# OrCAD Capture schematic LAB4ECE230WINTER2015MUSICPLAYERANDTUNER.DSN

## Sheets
1 part2LCDtuner: size A
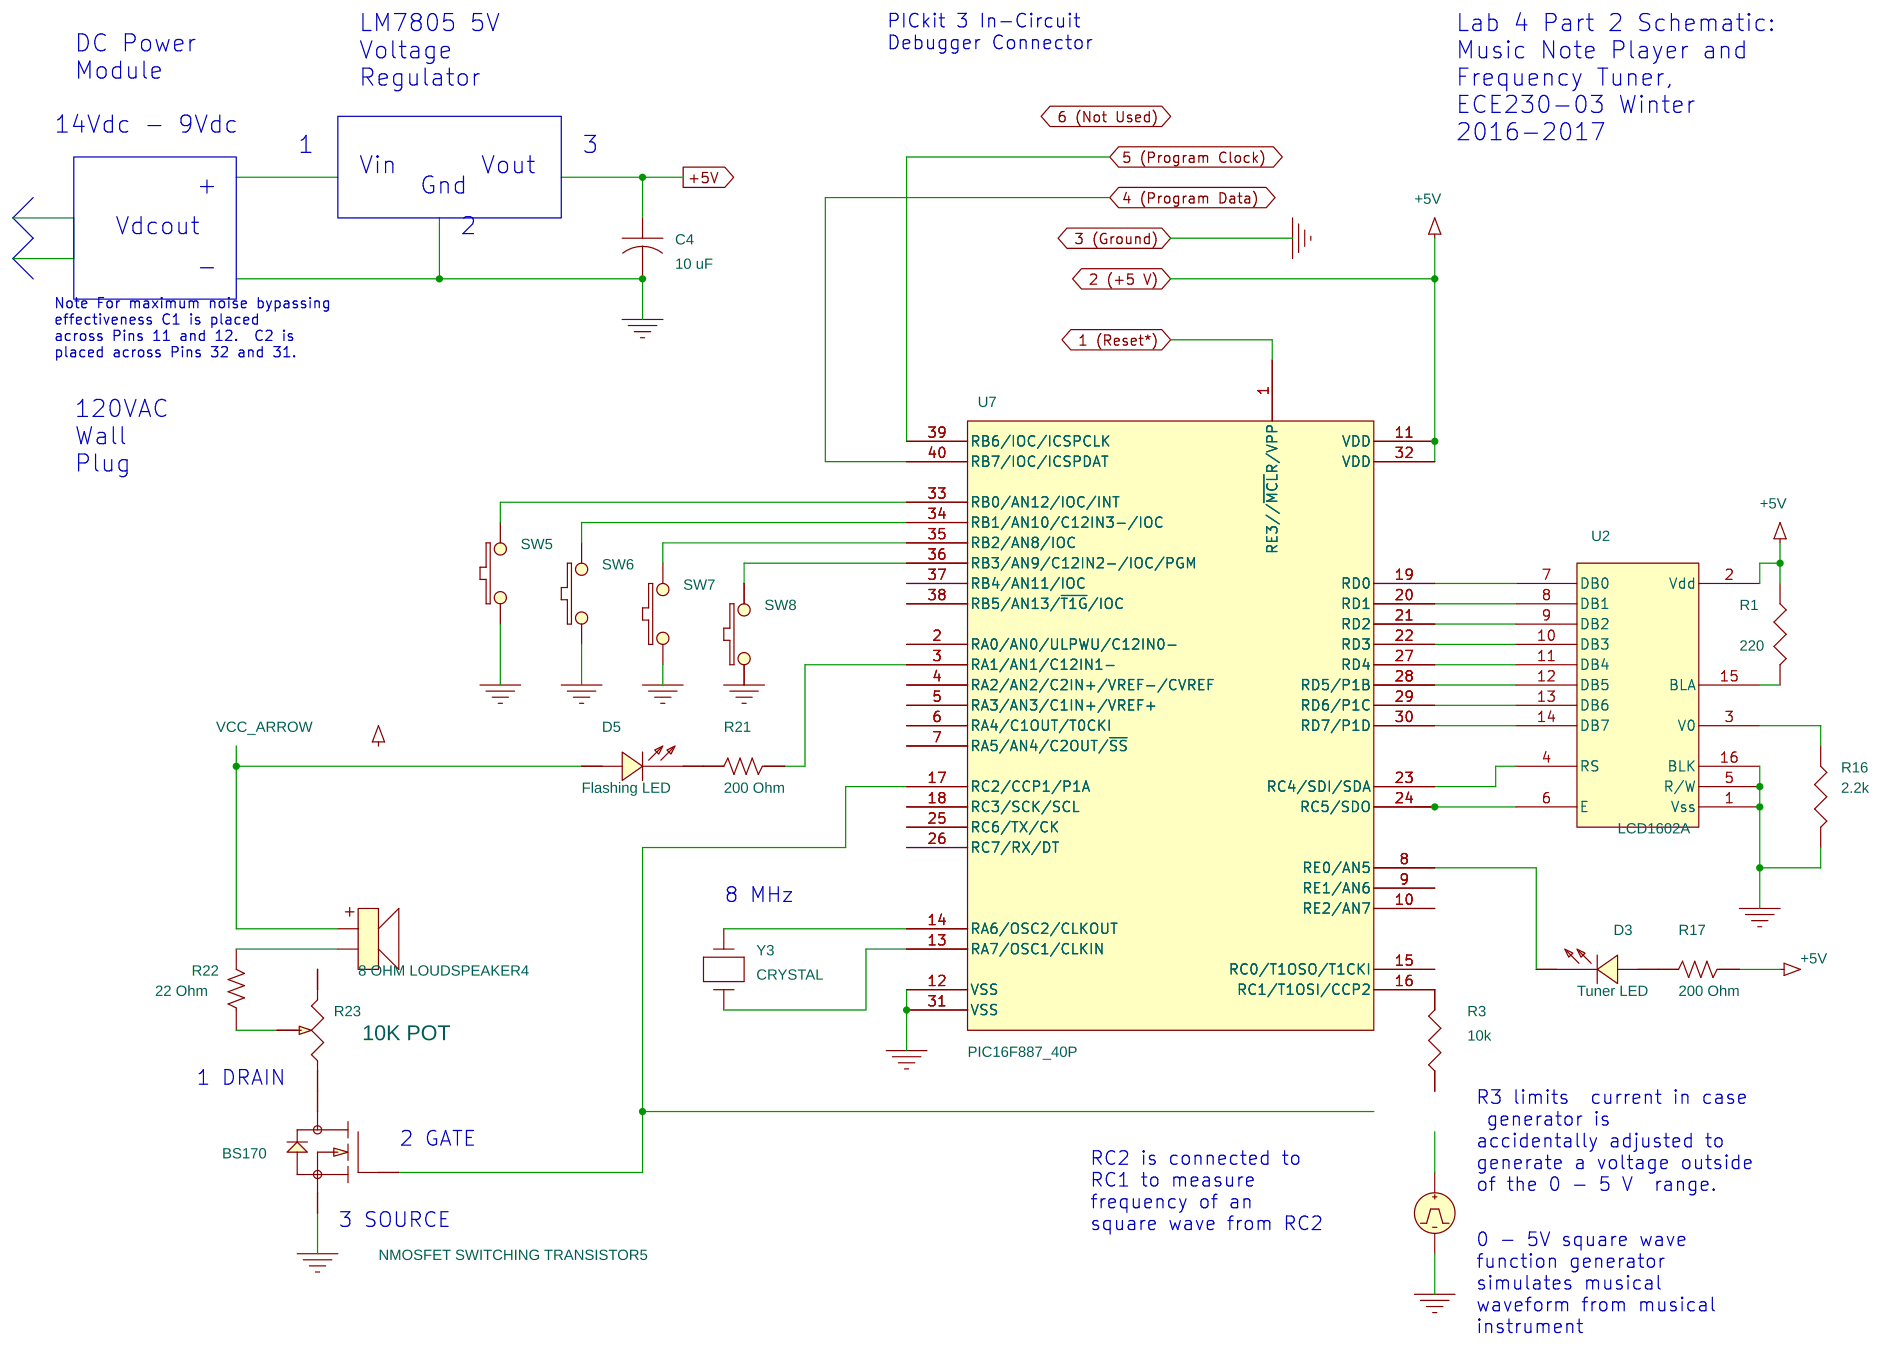
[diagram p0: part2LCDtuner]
2 part1MusicNotePlayer: size A
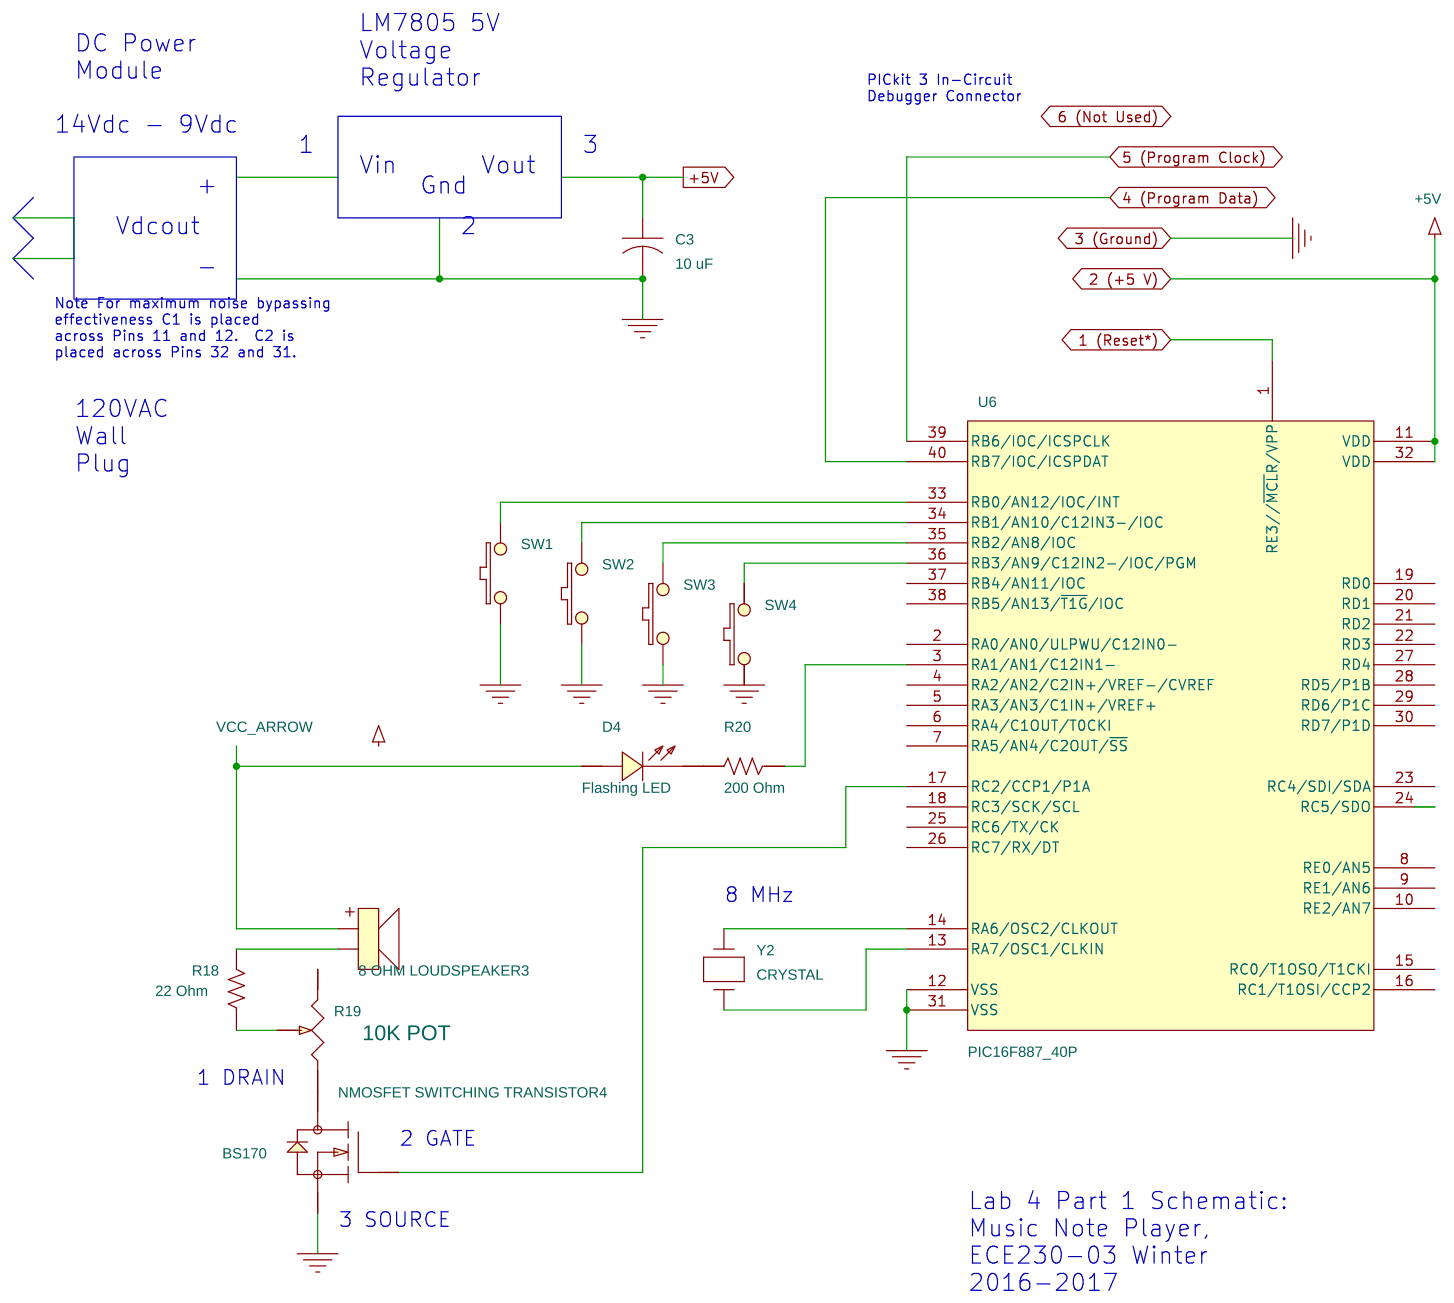
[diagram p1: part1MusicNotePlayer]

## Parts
sheet part1MusicNotePlayer
8 OHM LOUDSPEAKER3  8  [R1/4W]
C3  10 uF
D4  Flashing LED
NMOSFET SWITCHING TRANSISTOR4  BS170
R18  22 Ohm  [AX/RC05]
R19  10K POT
R20  200 Ohm  [AX/RC05]
SW1  SW PUSHBUTTON
SW2  SW PUSHBUTTON
SW3  SW PUSHBUTTON
SW4  SW PUSHBUTTON
U6  PIC16F887_40P
Y2  CRYSTAL
sheet part2LCDtuner
8 OHM LOUDSPEAKER4  8  [R1/4W]
C4  10 uF
D3  Tuner LED
D5  Flashing LED
NMOSFET SWITCHING TRANSISTOR5  BS170
R1  220
R3  10k
R16  2.2k
R17  200 Ohm  [AX/RC05]
R21  200 Ohm  [AX/RC05]
R22  22 Ohm  [AX/RC05]
R23  10K POT
SW5  SW PUSHBUTTON
SW6  SW PUSHBUTTON
SW7  SW PUSHBUTTON
SW8  SW PUSHBUTTON
U2  LCD1602A
U7  PIC16F887_40P
V1  VPULSE
Y3  CRYSTAL

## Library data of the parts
8 OHM LOUDSPEAKER3 8 OHM LOUDSPEAKER4 = Speaker
C3 C4 = C
D3-D5 = LED
NMOSFET SWITCHING TRANSISTOR4 NMOSFET SWITCHING TRANSISTOR5 = 2N7000
R17 R18 R20-R22 = R_v2
R19 R23 = POT
SW1-SW8 = SW_PUSHBUTTON
U6 U7 = PIC16F887_8: ICA_MFR_NAME: Microchip; ICA_PARTNUM: $$48491116942$$PIC16F887-I/P; Part Number: TMP-13
Y2 Y3 = CRYSTAL
R1 R3 R16 = R
U2 = LCD1602A_4
V1 = VPULSE

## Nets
+5V: C3.1 C4.1 R1.1 R17.1 U2.2(Vdd) U6.11(VDD) U6.32(VDD) U7.11(VDD) U7.32(VDD)
GND: C3.2 C4.2 NMOSFET SWITCHING TRANSISTOR4.1(SOURCE) NMOSFET SWITCHING TRANSISTOR5.1(SOURCE) R16.2 SW1.2 SW2.2 SW3.2 SW4.2 SW5.2 SW6.2 SW7.2 SW8.2 U2.1(Vss) U2.5(R/W) U2.16(BLK) U6.12(VSS) U6.31(VSS) U7.12(VSS) U7.31(VSS) V1.2(-)
1 (Reset*): U6.1(RE3//~{MCL}R/VPP) U7.1(RE3//~{MCL}R/VPP)
4 (Program Data): U6.40(RB7/IOC/ICSPDAT) U7.40(RB7/IOC/ICSPDAT)
5 (Program Clock): U6.39(RB6/IOC/ICSPCLK) U7.39(RB6/IOC/ICSPCLK)
N21825: U2.7(DB0) U7.19(RD0)
N21827: U2.8(DB1) U7.20(RD1)
N21829: U2.9(DB2) U7.21(RD2)
N21831: U2.10(DB3) U7.22(RD3)
N21833: U2.11(DB4) U7.27(RD4)
N21835: U2.12(DB5) U7.28(RD5/P1B)
N21837: U2.13(DB6) U7.29(RD6/P1C)
N21839: U2.14(DB7) U7.30(RD7/P1D)
N21902: U2.4(RS) U7.23(RC4/SDI/SDA)
N21908: U2.6(E) U7.24(RC5/SDO)
N23237: R16.1 U2.3(V0)
N25464: D3.1(CATHODE) U7.8(RE0/AN5)
N26566: NMOSFET SWITCHING TRANSISTOR4.2(GATE) U6.17(RC2/CCP1/P1A)
N26664: 8 OHM LOUDSPEAKER3.1 D4.2(ANODE)
N26694: 8 OHM LOUDSPEAKER3.2 R18.2
N26698: R18.1 R19.2(WIPER)
N26762: SW4.1 U6.36(RB3/AN9/C12IN2-/IOC/PGM)
N26770: SW3.1 U6.35(RB2/AN8/IOC)
N26778: SW2.1 U6.34(RB1/AN10/C12IN3-/IOC)
N26786: SW1.1 U6.33(RB0/AN12/IOC/INT)
N26858: R20.1 U6.3(RA1/AN1/C12IN1-)
N28656: R1.2 U2.15(BLA)
N70784: U6.14(RA6/OSC2/CLKOUT) Y2.1
N70808: U6.13(RA7/OSC1/CLKIN) Y2.2
N71514: NMOSFET SWITCHING TRANSISTOR4.3(DRAIN) R19.1(A)
N71515: D4.1(CATHODE) R20.2
N72376: D3.2(ANODE) R17.2
N73512: SW5.1 U7.33(RB0/AN12/IOC/INT)
N73524: SW6.1 U7.34(RB1/AN10/C12IN3-/IOC)
N73554: SW7.1 U7.35(RB2/AN8/IOC)
N73584: SW8.1 U7.36(RB3/AN9/C12IN2-/IOC/PGM)
N73644: R21.1 U7.3(RA1/AN1/C12IN1-)
N73674: 8 OHM LOUDSPEAKER4.1 D5.2(ANODE)
N73722: NMOSFET SWITCHING TRANSISTOR5.2(GATE) U7.17(RC2/CCP1/P1A)
N73760: U7.14(RA6/OSC2/CLKOUT) Y3.1
N73764: 8 OHM LOUDSPEAKER4.2 R22.2
N73784: U7.13(RA7/OSC1/CLKIN) Y3.2
N73842: R22.1 R23.2(WIPER)
N73983: D5.1(CATHODE) R21.2
N73985: R3.2 U7.16(RC1/T1OSI/CCP2)
N74089: NMOSFET SWITCHING TRANSISTOR5.3(DRAIN) R23.1(A)

Not connected (* = marked no-connect by the designer): R3 1; R19 3(B); R23 3(B); U6 2(RA0/AN0/ULPWU/C12IN0-) 4(RA2/AN2/C2IN+/VREF-/CVREF) 5(RA3/AN3/C1IN+/VREF+) 6(RA4/C1OUT/T0CKI) 7(RA5/AN4/C2OUT/~{SS}) 8(RE0/AN5) 9(RE1/AN6) 10(RE2/AN7) 15(RC0/T1OSO/T1CKI) 16(RC1/T1OSI/CCP2) 18(RC3/SCK/SCL) 19(RD0) 20(RD1) 21(RD2) 22(RD3) 23(RC4/SDI/SDA) 24(RC5/SDO) 25(RC6/TX/CK) 26(RC7/RX/DT) 27(RD4) 28(RD5/P1B) 29(RD6/P1C) 30(RD7/P1D) 37(RB4/AN11/IOC) 38(RB5/AN13/~{T1G}/IOC); U7 2(RA0/AN0/ULPWU/C12IN0-) 4(RA2/AN2/C2IN+/VREF-/CVREF) 5(RA3/AN3/C1IN+/VREF+) 6(RA4/C1OUT/T0CKI) 7(RA5/AN4/C2OUT/~{SS}) 9(RE1/AN6) 10(RE2/AN7) 15(RC0/T1OSO/T1CKI) 18(RC3/SCK/SCL) 25(RC6/TX/CK) 26(RC7/RX/DT) 37(RB4/AN11/IOC) 38(RB5/AN13/~{T1G}/IOC); V1 1(+)

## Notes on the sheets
sheet 1
- LM7805 5V
  Voltage
  Regulator
- PICkit 3 In-Circuit
  Debugger Connector
- Lab 4 Part 2 Schematic:
  Music Note Player and
  Frequency Tuner,
  ECE230-03 Winter
  2016-2017
- DC Power
  Module
- 14Vdc - 9Vdc
- 1
- 3
- Vin
- Vout
- +
- Gnd
- Vdcout
- 2
- -
- Note For maximum noise bypassing
  effectiveness C1 is placed
  across Pins 11 and 12.  C2 is
  placed across Pins 32 and 31.
- 120VAC
  Wall
  Plug
- 8 MHz
- 1 DRAIN
- R3 limits  current in case
   generator is
  accidentally adjusted to
  generate a voltage outside
  of the 0 - 5 V  range.
- 2 GATE
- RC2 is connected to
  RC1 to measure
  frequency of an
  square wave from RC2
- 3 SOURCE
- 0 - 5V square wave
  function generator
  simulates musical
  waveform from musical
  instrument
sheet 2
- LM7805 5V
  Voltage
  Regulator
- DC Power
  Module
- PICkit 3 In-Circuit
  Debugger Connector
- 14Vdc - 9Vdc
- 1
- 3
- Vin
- Vout
- +
- Gnd
- Vdcout
- 2
- -
- Note For maximum noise bypassing
  effectiveness C1 is placed
  across Pins 11 and 12.  C2 is
  placed across Pins 32 and 31.
- 120VAC
  Wall
  Plug
- 8 MHz
- 1 DRAIN
- 2 GATE
- Lab 4 Part 1 Schematic:
  Music Note Player,
  ECE230-03 Winter
  2016-2017
- 3 SOURCE
